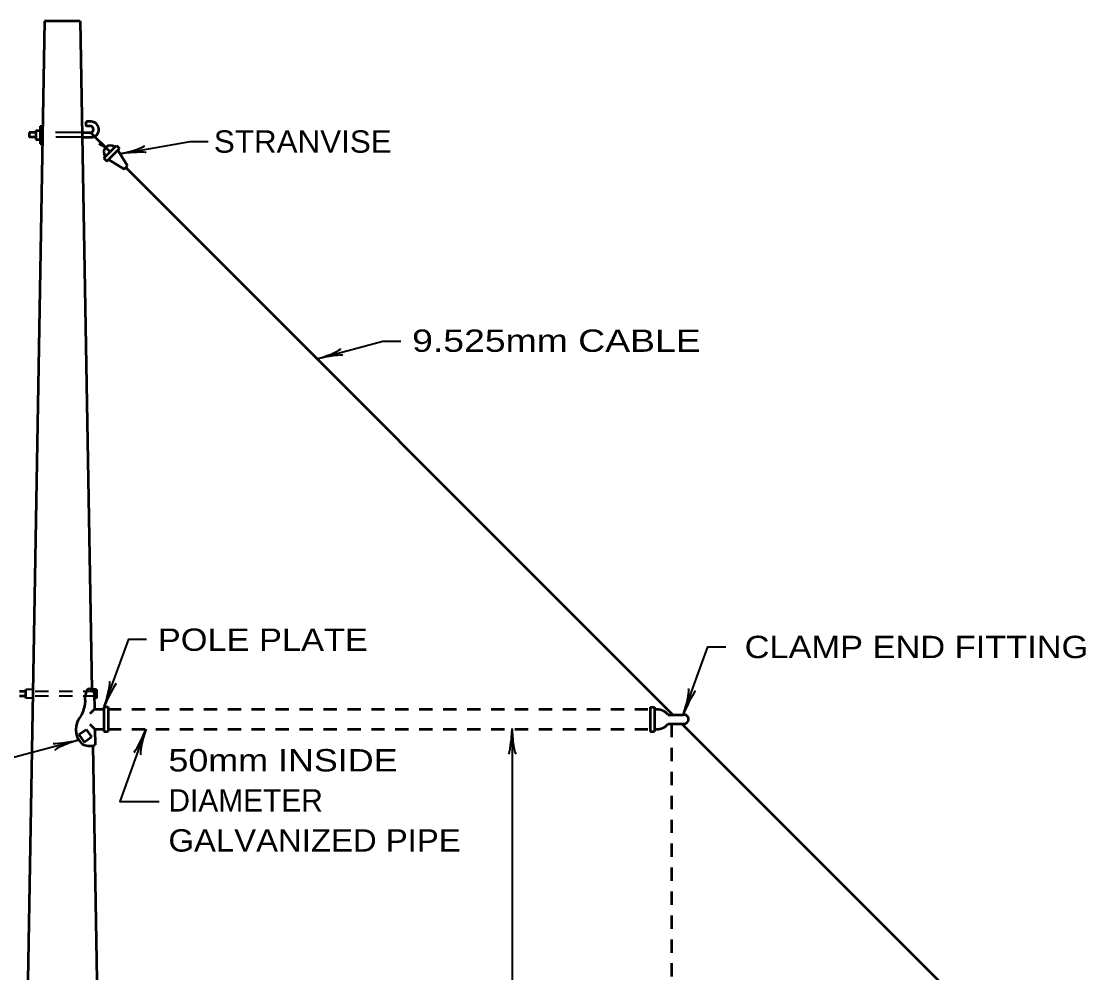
# Model space of a CAD drawing. Extents: x -34 to 821, y -14 to 530.
# Drawn here: x 373.2 to 517.2, y 128.9 to 257.7 of the extents above; entities that cross this region are included whole.
import ezdxf

# ---------------------------------------------------------------- set-up
doc = ezdxf.new("R2010")
doc.units = 0
doc.header["$LTSCALE"] = 1.2
doc.linetypes.add('MEDIUM_DASHED', pattern=[4.5, 3, -1.5])
doc.linetypes.add('SHORT_DASHED', pattern=[2.7, 1.5, -1.2])
doc.layers.add('1', color=7, linetype='Continuous', lineweight=53)

msp = doc.modelspace()

# ---------------------------------------------------------------- linework, layer by layer
at = {"layer": '1'}
for p, q in [((376.295, 257.658), (373.223, 82.29)), ((381.119, 257.658), (376.295, 257.658)), ((381.119, 257.658), (382.703, 167.25)), ((375.719, 243.474), (375.719, 241.074)), ((375.719, 243.474), (376.031, 243.474)), ((382.607, 244.098), (381.983, 244.098)), ((382.607, 243.474), (381.983, 243.474)), ((375.119, 242.586), (374.207, 242.586)), ((374.207, 242.586), (374.207, 241.962)), ((375.119, 242.874), (375.119, 241.674)), ((375.119, 242.874), (375.695, 242.874)), ((381.383, 242.586), (382.607, 242.586)), ((382.583, 242.562), (385.151, 240.018)), ((375.119, 241.962), (374.207, 241.962)), ((375.119, 241.674), (375.719, 241.674)), ((375.719, 241.074), (375.983, 241.074)), ((381.407, 241.962), (382.727, 241.962)), ((384.575, 240.594), (383.711, 241.074)), ((384.311, 239.154), (386.015, 240.858)), ((386.015, 240.858), (386.447, 240.426)), ((384.311, 239.154), (384.743, 238.722)), ((384.743, 238.722), (386.447, 240.426)), ((386.231, 240.21), (387.503, 238.074)), ((384.935, 238.938), (387.095, 237.666)), ((387.095, 237.666), (387.503, 238.074)), ((387.287, 237.858), (461.279, 163.866)), ((373.775, 166.05), (373.775, 167.25)), ((383.327, 167.25), (382.631, 167.25)), ((383.327, 167.25), (383.327, 166.05)), ((373.775, 166.938), (372.887, 166.938)), ((373.775, 166.338), (372.887, 166.338)), ((383.015, 166.746), (383.039, 164.562)), ((383.327, 166.05), (383.015, 166.05)), ((383.039, 164.562), (382.415, 163.914)), ((383.039, 164.562), (384.311, 164.562)), ((384.311, 164.874), (384.311, 161.538)), ((384.311, 164.874), (384.911, 164.874)), ((384.911, 164.874), (384.911, 161.538)), ((458.255, 164.85), (458.255, 161.538)), ((458.255, 164.85), (458.855, 164.85)), ((458.855, 164.85), (458.855, 161.538)), ((460.703, 163.794), (462.791, 163.794)), ((380.951, 161.13), (381.935, 161.826)), ((381.935, 161.826), (382.631, 160.818)), ((383.087, 161.85), (382.463, 162.498)), ((383.087, 161.85), (383.135, 159.738)), ((383.087, 161.85), (384.311, 161.85)), ((384.311, 161.538), (384.911, 161.538)), ((458.255, 161.538), (458.855, 161.538)), ((460.703, 162.57), (462.887, 162.594)), ((462.551, 162.594), (516.047, 109.122)), ((380.951, 161.13), (381.647, 160.122)), ((381.647, 160.122), (382.631, 160.818)), ((382.823, 159.642), (384.191, 82.29))]:
    msp.add_line(p, q, dxfattribs=at)
at = {"layer": '1', "linetype": 'MEDIUM_DASHED', "lineweight": 40}
for p, q in [((381.383, 242.586), (376.031, 242.586)), ((381.407, 241.962), (376.007, 241.962))]:
    msp.add_line(p, q, dxfattribs=at)
at = {"layer": '1', "lineweight": 40}
for p, q in [((374.711, 167.25), (373.775, 167.25)), ((374.687, 166.05), (373.775, 166.05))]:
    msp.add_line(p, q, dxfattribs=at)
at = {"layer": '1', "linetype": 'SHORT_DASHED', "lineweight": 40}
for p, q in [((383.327, 166.338), (374.687, 166.338)), ((383.303, 166.938), (374.711, 166.938))]:
    msp.add_line(p, q, dxfattribs=at)
at = {"layer": '1', "linetype": 'SHORT_DASHED'}
for p, q in [((384.887, 164.562), (458.255, 164.562)), ((384.887, 161.85), (458.255, 161.85)), ((461.135, 162.57), (461.135, 94.53))]:
    msp.add_line(p, q, dxfattribs=at)
at = {"layer": '1', "lineweight": 35}
for points in [[(386.519, 239.73), (396.023, 241.41), (398.447, 241.41)], [(413.183, 211.986), (422.087, 214.362), (424.511, 214.362)], [(384.383, 164.922), (387.695, 174.018), (390.095, 174.018)], [(462.767, 163.914), (466.079, 172.986), (468.503, 172.986)], [(390.023, 161.85), (386.471, 152.082), (391.823, 152.082)], [(439.583, 161.946), (439.583, 82.41), (439.583, 60.282)], [(380.927, 160.386), (371.591, 157.89), (369.167, 157.89)]]:
    msp.add_lwpolyline(points, dxfattribs=at)
at = {"layer": '1'}
for centre, radius, start, end in [((382.334, 243.784), 0.457, 138.58649, 221.41351), ((382.44, 243.028), 0.48, 289.03349, 70.96651), ((382.57, 243.022), 1.065, 278.54206, 88.56984), ((385.218, 239.949), 0.911, 50.20411, 219.79589), ((384.361, 165.958), 2.602, 151.6071, 191.23066), ((382.409, 166.692), 0.606, 5.14198, 123.76222), ((377.019, 165.967), 4.817, 331.99837, 353.85569), ((459.126, 162.491), 2.043, 39.94521, 97.50756), ((383.246, 161.825), 2.727, 136.38146, 225.27926), ((462.842, 163.193), 0.607, 265.53287, 94.46714), ((459.126, 163.892), 2.043, 262.49244, 320.05479), ((382.404, 161.784), 2.181, 240.4205, 289.57853)]:
    msp.add_arc(centre, radius, start, end, dxfattribs=at)
at = {"layer": '1', "lineweight": 40}
for centre, major_axis, ratio, start_param, end_param in [((387.763, 240.291), (-2.094, -0.561), 0.122415, 0.8963533, 3.1415927), ((387.9, 239.716), (2.129, 0.16), 0.07063, 6.2823074, 8.5597026), ((414.373, 212.646), (-2.037, -0.742), 0.122415, 0.8963533, 3.1415927), ((414.373, 212.646), (-2.037, -0.742), 0.122415, 0.8963533, 3.1415927), ((414.56, 212.085), (2.107, 0.345), 0.07063, 6.2823074, 8.5597026), ((414.56, 212.085), (2.107, 0.345), 0.07063, 6.2823074, 8.5597026), ((384.515, 166.281), (-0.561, -2.094), 0.122415, 0.8963533, 3.1415927), ((385.082, 166.112), (-0.926, -1.924), 0.07063, 3.1407148, 5.41811), ((462.902, 165.258), (-0.561, -2.094), 0.122415, 0.8963533, 3.1415927), ((463.469, 165.089), (-0.926, -1.924), 0.07063, 3.1407148, 5.41811), ((389.325, 160.659), (-0.926, -1.924), 0.07063, 6.2823074, 8.5597026), ((389.892, 160.491), (0.561, 2.094), 0.122415, 0.8963533, 3.1415927), ((439.323, 160.593), (-0.212, -2.125), 0.07063, 6.2823074, 8.5597026), ((439.913, 160.628), (-0.189, 2.16), 0.122415, 0.8963533, 3.1415927), ((379.553, 160.282), (-2.107, -0.345), 0.07063, 6.2823074, 8.5597026), ((379.74, 159.721), (2.038, 0.741), 0.122415, 0.8963533, 3.1415927)]:
    msp.add_ellipse(centre, major_axis=major_axis, ratio=ratio, start_param=start_param, end_param=end_param, dxfattribs=at)

# ---------------------------------------------------------------- texts
at = {"layer": '1'}
for s, width, p in [('STRANVISE', 1.05, (399.215, 239.874)), ('9.525mm CABLE', 1.25, (426.047, 212.922)), ('POLE PLATE', 1.15, (391.631, 172.458)), ('CLAMP END FITTING', 1.15, (471.047, 171.474)), ('50mm INSIDE', 1.2, (393.066, 156.138)), ('GALVANIZED PIPE', 1.1, (393.066, 145.29))]:
    msp.add_text(s, height=3.024, dxfattribs=dict(at, width=width)).set_placement(p)
msp.add_text('DIAMETER', height=3.024, dxfattribs=at).set_placement((393.066, 150.714))

doc.saveas('drawing.dxf')
